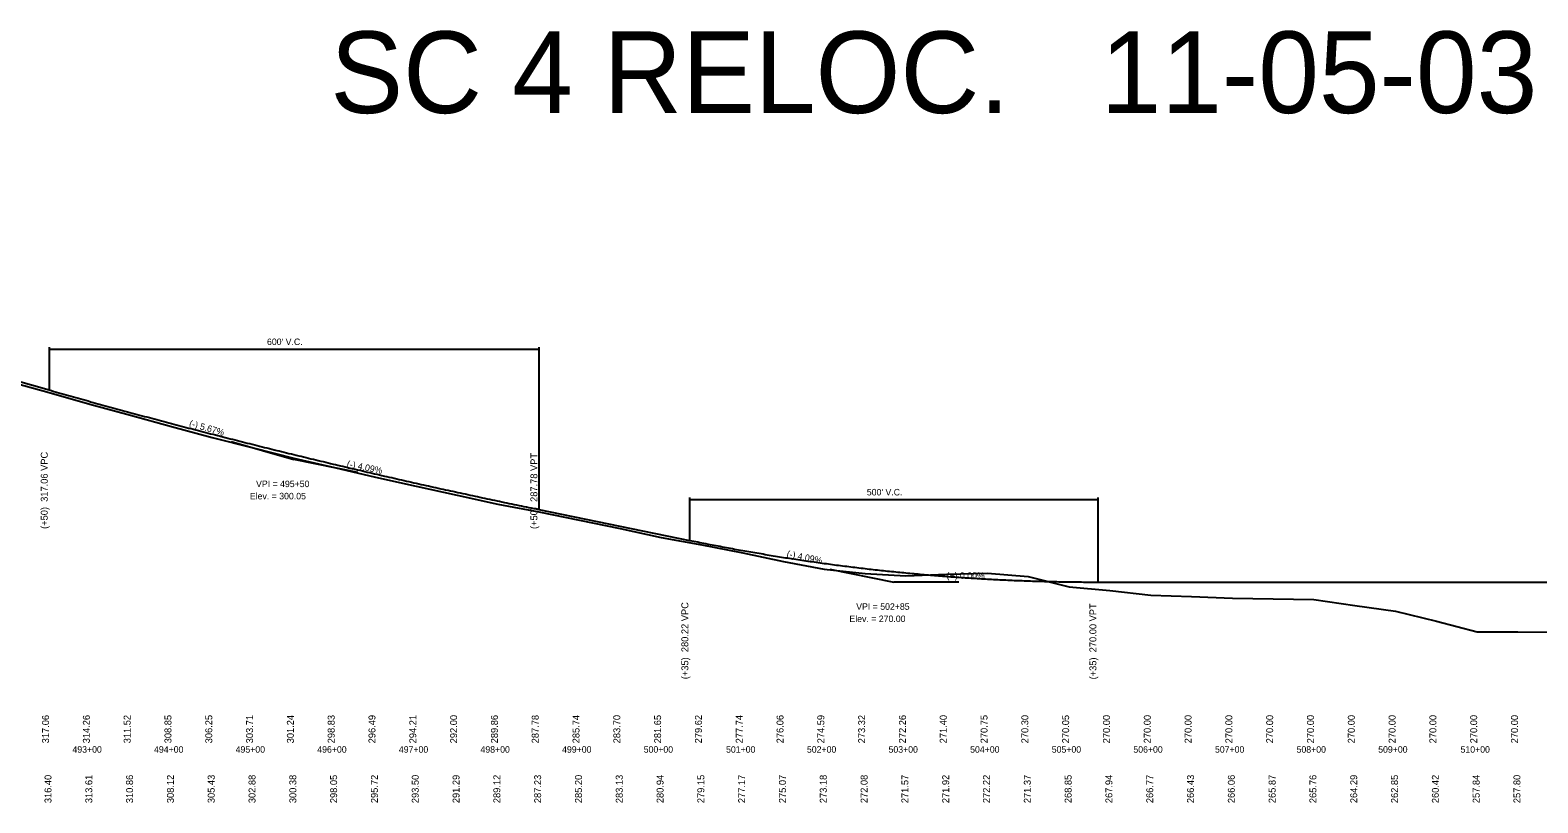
# Model space of a CAD drawing. Extents: x 1354 to 11940, y 17935 to 18885.
# Drawn here: x 3167 to 5014, y 17938 to 18885 of the extents above; entities that cross this region are included whole.
import ezdxf

# ---------------------------------------------------------------- set-up
doc = ezdxf.new("R2010")
doc.units = 0
for name, color, linetype in [('Level 1', 7, 'Continuous'), ('Level 40', 7, 'Continuous'), ('Level 41', 7, 'Continuous'), ('Level 42', 7, 'Continuous'), ('Level 43', 7, 'Continuous'), ('Level 45', 7, 'Continuous')]:
    doc.layers.add(name, color=color, linetype=linetype)

msp = doc.modelspace()

# ---------------------------------------------------------------- linework, layer by layer
at = {"layer": 'Level 40'}
msp.add_lwpolyline([(3139.7, 18454.7), (3189.7, 18440.5), (3239.7, 18426.6), (3289.7, 18412.8), (3339.7, 18399.1), (3389.7, 18385.6), (3439.7, 18372.9), (3489.7, 18360.4), (3539.7, 18348.7), (3589.7, 18337.1), (3639.7, 18326), (3689.7, 18315), (3739.7, 18304.1), (3789.7, 18294.6), (3839.7, 18284.5), (3889.7, 18274.1), (3939.7, 18263.2), (3989.7, 18254.3), (4039.7, 18244.4), (4089.7, 18233.9), (4139.7, 18224.4), (4189.7, 18218.9), (4239.7, 18216.3), (4289.7, 18218.1), (4339.7, 18219.6), (4389.7, 18215.3), (4439.7, 18202.8), (4489.7, 18198.2), (4539.7, 18192.3), (4589.7, 18190.7), (4639.7, 18188.8), (4689.7, 18187.8), (4739.7, 18187.3), (4789.7, 18180), (4839.7, 18172.7), (4889.7, 18160.6), (4939.7, 18147.7), (4989.7, 18147.5), (5039.7, 18147)], dxfattribs=at)
at = {"layer": 'Level 41'}
for p, q in [((3189.7, 18496.3), (3189.7, 18443.8)), ((3189.7, 18493.8), (3789.7, 18493.8)), ((3789.7, 18496.3), (3789.7, 18297.4)), ((3412.8, 18380.6), (3489.7, 18358.8)), ((3568.1, 18342.7), (3489.7, 18358.8)), ((3974.7, 18312.1), (3974.7, 18259.6)), ((3974.7, 18309.6), (4474.7, 18309.6)), ((4474.7, 18312.1), (4474.7, 18208.5)), ((4146.4, 18224.5), (4224.7, 18208.5)), ((4304.7, 18208.5), (4224.7, 18208.5))]:
    msp.add_line(p, q, dxfattribs=at)
at = {"layer": 'Level 45'}
for p, q in [((2939.7, 18514.7), (3189.7, 18443.8)), ((3789.7, 18297.4), (3974.7, 18259.6)), ((4474.7, 18208.5), (8339.7, 18208.5))]:
    msp.add_line(p, q, dxfattribs=at)
for points in [[(3189.7, 18443.8), (3201.7, 18440.4), (3213.7, 18437), (3225.7, 18433.7), (3237.7, 18430.3), (3249.7, 18427), (3261.7, 18423.7), (3273.7, 18420.4), (3285.7, 18417.2), (3297.7, 18413.9), (3309.7, 18410.7), (3321.7, 18407.5), (3333.7, 18404.3), (3345.7, 18401.2), (3357.7, 18398), (3369.7, 18394.9), (3381.7, 18391.8), (3393.7, 18388.7), (3405.7, 18385.6), (3417.7, 18382.6), (3429.7, 18379.6), (3441.7, 18376.5), (3453.7, 18373.5), (3465.7, 18370.6), (3477.7, 18367.6), (3489.7, 18364.7), (3501.7, 18361.8), (3513.7, 18358.9), (3525.7, 18356), (3537.7, 18353.1), (3549.7, 18350.3), (3561.7, 18347.5), (3573.7, 18344.7), (3585.7, 18341.9), (3597.7, 18339.1), (3609.7, 18336.4), (3621.7, 18333.6), (3633.7, 18330.9), (3645.7, 18328.2), (3657.7, 18325.6), (3669.7, 18322.9), (3681.7, 18320.3), (3693.7, 18317.7), (3705.7, 18315.1), (3717.7, 18312.5), (3729.7, 18309.9), (3741.7, 18307.4), (3753.7, 18304.9), (3765.7, 18302.4), (3777.7, 18299.9), (3789.7, 18297.4)], [(3974.7, 18259.6), (3984.7, 18257.6), (3994.7, 18255.6), (4004.7, 18253.7), (4014.7, 18251.8), (4024.7, 18249.9), (4034.7, 18248.1), (4044.7, 18246.3), (4054.7, 18244.6), (4064.7, 18242.9), (4074.7, 18241.2), (4084.7, 18239.6), (4094.7, 18238), (4104.7, 18236.5), (4114.7, 18235), (4124.7, 18233.5), (4134.7, 18232.1), (4144.7, 18230.8), (4154.7, 18229.4), (4164.7, 18228.1), (4174.7, 18226.9), (4184.7, 18225.7), (4194.7, 18224.5), (4204.7, 18223.4), (4214.7, 18222.3), (4224.7, 18221.3), (4234.7, 18220.3), (4244.7, 18219.3), (4254.7, 18218.4), (4264.7, 18217.5), (4274.7, 18216.7), (4284.7, 18215.9), (4294.7, 18215.1), (4304.7, 18214.4), (4314.7, 18213.7), (4324.7, 18213.1), (4334.7, 18212.5), (4344.7, 18212), (4354.7, 18211.4), (4364.7, 18211), (4374.7, 18210.5), (4384.7, 18210.2), (4394.7, 18209.8), (4404.7, 18209.5), (4414.7, 18209.2), (4424.7, 18209), (4434.7, 18208.8), (4444.7, 18208.7), (4454.7, 18208.6), (4464.7, 18208.5), (4474.7, 18208.5)]]:
    msp.add_spline(points, degree=3, dxfattribs=at)

# ---------------------------------------------------------------- texts
at = {"layer": 'Level 1'}
msp.add_text('SC 4 RELOC.   11-05-03', height=100, dxfattribs=at).set_placement((3534.4, 18783))
at = {"layer": 'Level 41'}
for s, p in [("600' V.C.", (3456.8, 18498.8)), ('VPI = 495+50', (3443.4, 18324.8)), ('Elev. = 300.05', (3435.8, 18309.8)), ("500' V.C.", (4191.8, 18314.6)), ('(+) 0.00%', (4289.6, 18212.5)), ('VPI = 502+85', (4178.8, 18174.5)), ('Elev. = 270.00', (4170.5, 18159.5))]:
    msp.add_text(s, height=8, dxfattribs=at).set_placement(p)
for s, height, rotation, p in [('(-) 5.67%', 8, 344.174, (3360.8, 18399.5)), ('(+50)  317.06 VPC', 8.5, 90, (3188.1, 18273.6)), ('(+50)  287.78 VPT', 8.5, 90, (3788.1, 18273.5)), ('(-) 4.09%', 8, 348.4467, (3554.1, 18349.7)), ('(-) 4.09%', 8, 348.4467, (4093.1, 18239.5)), ('(+35)  280.22 VPC', 8.5, 90, (3973.1, 18089.5)), ('(+35)  270.00 VPT', 8.5, 90, (4473.1, 18089.3))]:
    msp.add_text(s, height=height, rotation=rotation, dxfattribs=at).set_placement(p)
at = {"layer": 'Level 42'}
for s, p in [('493+00', (3218.4, 17999.5)), ('494+00', (3318.4, 17999.5)), ('495+00', (3418.4, 17999.5)), ('496+00', (3518.4, 17999.5)), ('497+00', (3618.4, 17999.5)), ('498+00', (3718.4, 17999.5)), ('499+00', (3818.4, 17999.5)), ('500+00', (3918.4, 17999.5)), ('501+00', (4019.3, 17999.5)), ('502+00', (4118.4, 17999.5)), ('503+00', (4218.4, 17999.5)), ('504+00', (4318.4, 17999.5)), ('505+00', (4418.4, 17999.5)), ('506+00', (4518.4, 17999.5)), ('507+00', (4618.4, 17999.5)), ('508+00', (4718.4, 17999.5)), ('509+00', (4818.4, 17999.5)), ('510+00', (4919.3, 17999.5))]:
    msp.add_text(s, height=8, dxfattribs=at).set_placement(p)
at = {"layer": 'Level 43'}
for s, p in [('317.06', (3189.7, 18011)), ('314.26', (3239.7, 18011)), ('311.52', (3289.7, 18011)), ('308.85', (3339.7, 18011)), ('306.25', (3389.7, 18011)), ('303.71', (3439.7, 18011)), ('301.24', (3489.7, 18011)), ('298.83', (3539.7, 18011)), ('296.49', (3589.7, 18011)), ('294.21', (3639.7, 18011)), ('292.00', (3689.7, 18011)), ('289.86', (3739.7, 18011)), ('287.78', (3789.7, 18011)), ('285.74', (3839.7, 18011)), ('283.70', (3889.7, 18011)), ('281.65', (3939.7, 18011)), ('279.62', (3989.7, 18011)), ('277.74', (4039.7, 18011)), ('276.06', (4089.7, 18011)), ('274.59', (4139.7, 18011)), ('273.32', (4189.7, 18011)), ('272.26', (4239.7, 18011)), ('271.40', (4289.7, 18011)), ('270.75', (4339.7, 18011)), ('270.30', (4389.7, 18011)), ('270.05', (4439.7, 18011)), ('270.00', (4489.7, 18011)), ('270.00', (4539.7, 18011)), ('270.00', (4589.7, 18011)), ('270.00', (4639.7, 18011)), ('270.00', (4689.7, 18011)), ('270.00', (4739.7, 18011)), ('270.00', (4789.7, 18011)), ('270.00', (4839.7, 18011)), ('270.00', (4889.7, 18011)), ('270.00', (4939.7, 18011)), ('270.00', (4989.7, 18011)), ('316.40', (3192.7, 17937.7)), ('313.61', (3242.7, 17937.7)), ('310.86', (3292.7, 17937.7)), ('308.12', (3342.7, 17937.7)), ('305.43', (3392.7, 17937.7)), ('302.88', (3442.7, 17937.7)), ('300.38', (3492.7, 17937.7)), ('298.05', (3542.7, 17937.7)), ('295.72', (3592.7, 17937.7)), ('293.50', (3642.7, 17937.7)), ('291.29', (3692.7, 17937.7)), ('289.12', (3742.7, 17937.7)), ('287.23', (3792.7, 17937.7)), ('285.20', (3842.7, 17937.7)), ('283.13', (3892.7, 17937.7)), ('280.94', (3942.7, 17937.7)), ('279.15', (3992.7, 17937.7)), ('277.17', (4042.7, 17937.7)), ('275.07', (4092.7, 17937.7)), ('273.18', (4142.7, 17937.7)), ('272.08', (4192.7, 17937.7)), ('271.57', (4242.7, 17937.7)), ('271.92', (4292.7, 17937.7)), ('272.22', (4342.7, 17937.7)), ('271.37', (4392.7, 17937.7)), ('268.85', (4442.7, 17937.7)), ('267.94', (4492.7, 17937.7)), ('266.77', (4542.7, 17937.7)), ('266.43', (4592.7, 17937.7)), ('266.06', (4642.7, 17937.7)), ('265.87', (4692.7, 17937.7)), ('265.76', (4742.7, 17937.7)), ('264.29', (4792.7, 17937.7)), ('262.85', (4842.7, 17937.7)), ('260.42', (4892.7, 17937.7)), ('257.84', (4942.7, 17937.7)), ('257.80', (4992.7, 17937.7))]:
    msp.add_text(s, height=8.5, rotation=90, dxfattribs=at).set_placement(p)

doc.saveas('drawing.dxf')
